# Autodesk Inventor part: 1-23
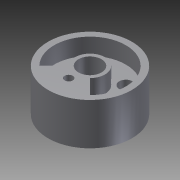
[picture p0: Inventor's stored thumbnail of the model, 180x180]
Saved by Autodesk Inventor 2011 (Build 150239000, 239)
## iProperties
Created: 2014-05
Part Number: 1-23
Document SubType Name: Modeling
Designer: 頔。
Density: 1 g/cm^3
Author: 頔。
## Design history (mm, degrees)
sketch "草图1"
  geometry: C1 r 25 at (0, 0); 1 further point
  constraints: 1 centre point, 1 coincident
  dimensions: "d0" = 50 diameter of C1
extrude "拉伸1" new body sketch "草图1" distance "d1" = 25; taper "d2" = 0 deg
sketch "草图2"
  geometry: L1 (-6.341, -6.341)-(-15.113, -15.113); L2 (0, 0)-(38.74, 0); L3 (0, 0)-(45.279, 0); L4 (6.341, -6.341)-(15.113, -15.113); C1 r 25 at (0, 0) reference; A1 r 21.373 centre (0, 0) between (15.113, -15.113) and (-15.113, -15.113); A2 r 8.968 centre (0, 0) between (6.341, -6.341) and (-6.341, -6.341)
  constraints: 8 end point, 4 point on circle, 2 centre point, 2 coincident, 2 horizontal
  dimensions: "d3" = 135 deg angle of L1 L2
extrude "拉伸2" cut sketch "草图2" distance "d5" = 10; taper "d6" = 0 deg
sketch "草图3"
  geometry: C1 r 25 at (0, 0) reference; C2 r 6.875 at (0, 0)
  constraints: 1 centre point, 1 coincident
extrude "拉伸3" cut sketch "草图3" distance "d7" = 10; taper "d8" = 0 deg
sketch "草图4"
  geometry: L1 (0, 0)-(36.913, 0); L2 (0, 0)-(39.951, 0); C1 r 4 at (-10.727, 10.727); C2 r 4 at (10.727, 10.727); A1 r 21.373 centre (0, 0) between (15.113, -15.113) and (-15.113, -15.113) reference
  constraints: 4 end point, 2 centre point, 2 horizontal
  dimensions: "d11" = 8 diameter of C1; "d12" = 8 diameter of C2
sketch "草图5"
  geometry: C1 r 6.875 at (0, 0) reference; C2 r 5.349 at (0, 0)
  constraints: 1 centre point, 1 coincident
extrude "拉伸4" cut sketch "草图4" stored distance "d13" = 10; taper "d14" = 0 deg
extrude "拉伸5" cut sketch "草图5" stored distance "d15" = 10; taper "d16" = 0 deg
sketch "草图6"
  geometry: C1 r 3.5 at (0, -12.704)
  constraints: 1 centre point
  dimensions: "d17" = 7 diameter of C1
extrude "拉伸6" cut sketch "草图6" distance "d18" = 7; taper "d19" = 0 deg
sketch "草图7"
  geometry: C1 r 3.5 at (0, 0) reference; C2 r 2.431 at (0, 0); 1 further point
  constraints: 1 centre point, 1 coincident
extrude "拉伸7" cut sketch "草图7" stored distance "d20" = 7; taper "d21" = 0 deg
node "实体1"
other parameters: "d4" = 45 deg
